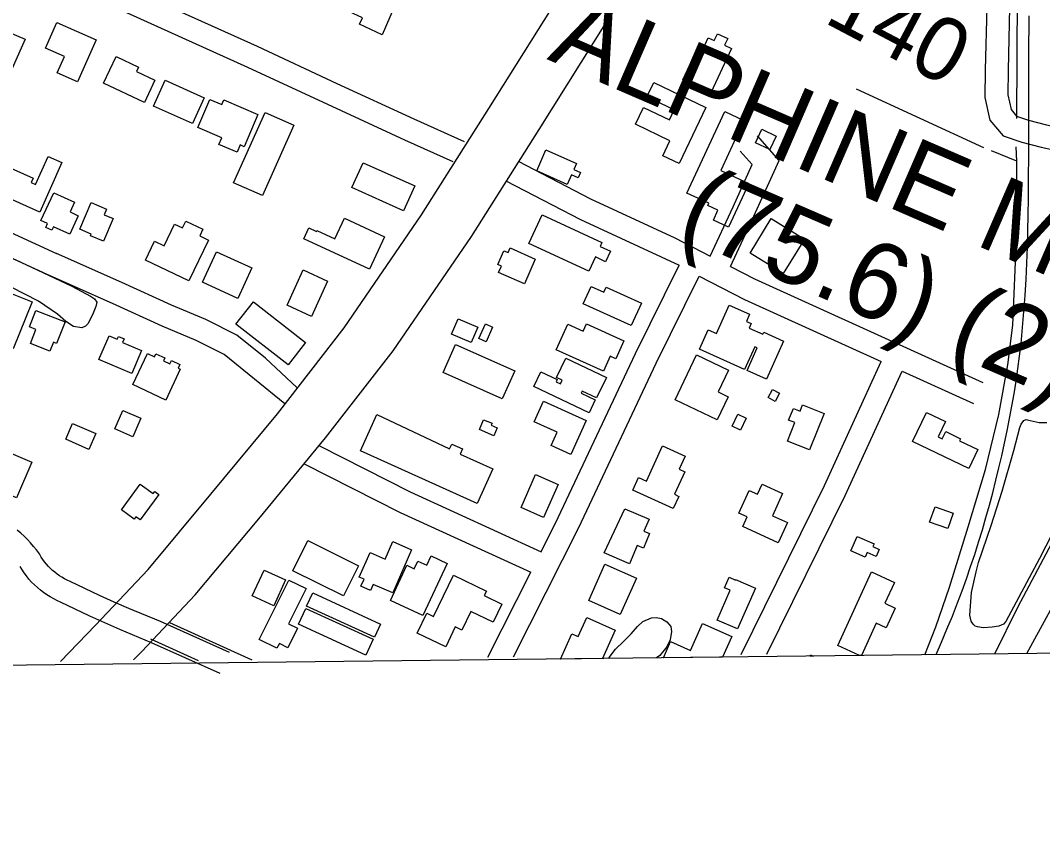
# Model space of a CAD drawing. Extents: x 3683402 to 3721514, y 487807 to 513565.
# Drawn here: x 3706941 to 3708279, y 493222 to 494291 of the extents above; entities that cross this region are included whole.
import ezdxf

# ---------------------------------------------------------------- set-up
doc = ezdxf.new("R2010")
doc.units = 0
for name, color, linetype in [('V-BLDG-OTLN', 7, 'Continuous'), ('V-CHAN-NAID', 7, 'Continuous'), ('V-GRID-FRAM', 7, 'Continuous'), ('V-LEVE-TOET', 7, 'Continuous'), ('V-RAIL-TRAK', 7, 'Continuous'), ('V-RIVR-RANG-IDEN', 7, 'Continuous'), ('V-ROAD-CNTR', 7, 'Continuous'), ('V-SITE-VEGE', 7, 'Continuous'), ('V-SURV-LINE', 7, 'Continuous'), ('V-TOPO-SHOR', 7, 'Continuous')]:
    doc.layers.add(name, color=color, linetype=linetype)

msp = doc.modelspace()

# ---------------------------------------------------------------- linework, layer by layer
at = {"layer": 'V-BLDG-OTLN'}
for p, q in [((3708011.4, 493472), (3708055.5, 493568.6)), ((3708055.5, 493568.6), (3708085.5, 493554.9)), ((3708085.5, 493554.9), (3708073, 493527.5)), ((3708073, 493527.5), (3708086.5, 493521.3)), ((3708086.5, 493521.3), (3708074.7, 493495.4)), ((3707671.4, 493483.8), (3707682.9, 493509.1)), ((3707682.9, 493509.1), (3707720, 493492.3)), ((3707720, 493492.3), (3707703.1, 493455.2)), ((3707818.7, 493465.7), (3707834.1, 493500.9)), ((3707834.1, 493500.9), (3707872.4, 493484.1)), ((3708061.5, 493501.5), (3708042.2, 493459.1)), ((3708074.7, 493495.4), (3708061.5, 493501.5)), ((3707648.3, 493454.5), (3707663.2, 493487.5)), ((3707663.2, 493487.5), (3707671.4, 493483.8)), ((3707783, 493456.1), (3707792.3, 493477.3)), ((3707792.3, 493477.3), (3707818.7, 493465.7)), ((3707872.4, 493484.1), (3707860.6, 493457)), ((3708039.7, 493459.1), (3708011.4, 493472)), ((3707703.1, 493455.2), (3707648.3, 493454.5)), ((3707860.6, 493457), (3707783, 493456.1)), ((3707974.9, 493458.3), (3707975.6, 493460)), ((3707979.7, 493458.4), (3707974.9, 493458.3)), ((3707975.6, 493460), (3707979.7, 493458.4)), ((3708042.2, 493459.1), (3708039.7, 493459.1))]:
    msp.add_line(p, q, dxfattribs=at)
for points in [[(3707356.7, 494301.7), (3707318.5, 494319.4), (3707331.8, 494347.9), (3707370.3, 494330), (3707363.3, 494314.8), (3707380.9, 494306.7), (3707392.8, 494337.8), (3707401.5, 494334.2), (3707402.3, 494335.9), (3707436.1, 494322.2), (3707415, 494272.3), (3707385.1, 494286.2), (3707389, 494294.7), (3707359.7, 494308.2)], [(3707040.3, 494265.7), (3707016, 494210.7), (3706989.3, 494222.5), (3706998.8, 494244), (3706974.1, 494255), (3706988.8, 494288.4)], [(3706892.2, 494212.3), (3706921.9, 494277.4), (3706947.4, 494266.5), (3706918, 494200.7)], [(3707872.1, 494254.5), (3707845.3, 494196.4), (3707808.5, 494213.4), (3707820.1, 494238.6), (3707826.6, 494235.7), (3707841.8, 494268.5), (3707849.6, 494264.8), (3707853.7, 494273.7), (3707867.2, 494267.4), (3707863.2, 494258.7)], [(3707103.6, 494183.8), (3707050.2, 494209.2), (3707066.7, 494243.9), (3707095.9, 494230.1), (3707093.1, 494224.2), (3707117.3, 494212.8)], [(3707130.6, 494212.9), (3707181.7, 494190), (3707166.4, 494156), (3707115.4, 494178.9)], [(3707770.3, 494210), (3707838.7, 494177.2), (3707803.6, 494103.8), (3707782.2, 494114), (3707791.6, 494133.6), (3707746.3, 494155.3), (3707756.8, 494177.2), (3707790.9, 494160.9), (3707797.1, 494173.9), (3707761.2, 494191)], [(3707207.5, 494187), (3707252.1, 494168.1), (3707234.2, 494125.8), (3707229, 494128), (3707225, 494118.5), (3707201.2, 494128.7), (3707204.9, 494137.4), (3707173.3, 494150.8), (3707189, 494187.7), (3707204.9, 494181)], [(3707813.7, 494065), (3707863.4, 494171.7), (3707888.5, 494160), (3707858.1, 494094.6), (3707895, 494077.4), (3707868.4, 494020.4), (3707848.4, 494029.6), (3707854.4, 494042.5), (3707841.1, 494048.8), (3707842.4, 494051.6)], [(3707299.2, 494153.8), (3707258, 494061.6), (3707220.3, 494078.4), (3707261.5, 494170.6)], [(3707911.9, 494148.6), (3707930.8, 494139.7), (3707922.5, 494122), (3707903.6, 494130.8)], [(3707629.3, 494121.5), (3707669.3, 494103.7), (3707665.8, 494095.8), (3707674.7, 494091.8), (3707671.6, 494084.9), (3707662.6, 494088.9), (3707657, 494076.4), (3707617.1, 494094.1)], [(3706966.5, 494040), (3706901, 494069.1), (3706916.1, 494103.2), (3706958.1, 494084.5), (3706955.5, 494078.7), (3706961.1, 494076.2), (3706977.5, 494113.1), (3706995.4, 494105.2)], [(3707442.7, 494041.7), (3707375.2, 494072.1), (3707389.9, 494104.7), (3707457.4, 494074.3)], [(3706968.1, 494029), (3706985.1, 494065.5), (3707012.1, 494053), (3707006.2, 494040.3), (3707017, 494035.3), (3707005.8, 494011.1), (3706984.7, 494020.9), (3706982.5, 494016.2), (3706974.5, 494019.9), (3706976.8, 494025)], [(3707018.8, 494017.6), (3707033.7, 494052.6), (3707053.9, 494044), (3707050.8, 494036.6), (3707062.8, 494031.5), (3707050.2, 494001.8), (3707033.1, 494009.1), (3707033.9, 494011.2)], [(3707187.3, 494003.4), (3707161.7, 493949.8), (3707104.8, 493977), (3707116.7, 494001.9), (3707129.3, 493995.9), (3707142.9, 494024.4), (3707153.5, 494019.4), (3707157.8, 494028.3), (3707180.1, 494017.6), (3707175.9, 494008.8)], [(3707398.1, 493965.1), (3707312.1, 494005.2), (3707318.8, 494019.5), (3707328.8, 494014.8), (3707329.3, 494015.9), (3707353, 494004.9), (3707365.7, 494032.3), (3707417.9, 494007.7)], [(3707624.2, 494036.4), (3707702.4, 494000.1), (3707700.2, 493995.2), (3707713.7, 493988.9), (3707707.3, 493975.1), (3707694, 493981.3), (3707685.2, 493962.5), (3707606.8, 493998.9)], [(3707924.3, 494031.6), (3707967.9, 494004.7), (3707940, 493959.5), (3707896.4, 493986.4)], [(3707198, 493988.1), (3707244.3, 493966.9), (3707226, 493926.9), (3707179.7, 493948.2)], [(3707601, 493946), (3707567.3, 493960.8), (3707571.1, 493969.4), (3707566.1, 493971.6), (3707574, 493989.5), (3707579.6, 493987.1), (3707582.2, 493993.1), (3707615.3, 493978.5)], [(3707290.3, 493918), (3707311.5, 493964.3), (3707343.4, 493949.7), (3707322.1, 493903.4)], [(3706956.7, 493922.4), (3706931.8, 493861.1), (3706894.8, 493876.2), (3706919.7, 493937.5)], [(3707754.2, 493920.8), (3707741, 493891.5), (3707678.1, 493919.9), (3707688.3, 493942.4), (3707704.9, 493935), (3707707.9, 493941.7)], [(3707291.7, 493840), (3707223.4, 493893.2), (3707246.2, 493922.4), (3707314.5, 493869.2)], [(3707889.4, 493833.8), (3707830.3, 493860.5), (3707841.7, 493885.9), (3707852.5, 493881), (3707869.2, 493918.2), (3707895.8, 493906.2), (3707891.6, 493896.9), (3707898.1, 493894), (3707895.4, 493888.1), (3707913.4, 493880), (3707914.5, 493882.6), (3707940.4, 493870.9), (3707918, 493821.1), (3707892.5, 493832.6), (3707905.9, 493862.4), (3707902.9, 493863.7)], [(3706999.7, 493896.4), (3706988.6, 493867.9), (3706984.4, 493869.5), (3706979.9, 493858), (3706954.4, 493868), (3706961.5, 493886.3), (3706953, 493889.6), (3706961.5, 493911.3)], [(3707514.3, 493900.3), (3707539.9, 493889.3), (3707531.2, 493869), (3707505.5, 493880)], [(3707541.5, 493874.4), (3707549.9, 493893.6), (3707559.2, 493889.5), (3707550.8, 493870.3)], [(3707704.4, 493831.6), (3707642.5, 493859.6), (3707657.7, 493893.2), (3707677.9, 493884), (3707682.3, 493893.7), (3707731.2, 493871.5), (3707720.6, 493848), (3707713.3, 493851.3)], [(3707086.9, 493828.6), (3707043.9, 493847), (3707057.2, 493878.1), (3707067.9, 493873.5), (3707069.5, 493877.2), (3707076.9, 493874.1), (3707074.8, 493869.3), (3707099.8, 493858.7)], [(3707571.9, 493795.5), (3707494.5, 493830), (3707510.8, 493866.7), (3707588.3, 493832.1)], [(3707131.6, 493793.7), (3707088.3, 493814), (3707107.4, 493854.9), (3707116.7, 493850.6), (3707118.5, 493854.4), (3707130.3, 493848.9), (3707128.5, 493845), (3707136.8, 493841.2), (3707138.9, 493845.7), (3707150, 493840.5), (3707147.6, 493835.4), (3707150.4, 493834.1)], [(3707853.6, 493768), (3707798.3, 493794.3), (3707826.2, 493853), (3707868.2, 493833), (3707854.6, 493804.6), (3707868, 493798.2)], [(3707685.9, 493777.1), (3707613.4, 493811.5), (3707622.5, 493830.8), (3707644, 493820.6), (3707642.6, 493817.7), (3707648.2, 493815), (3707650.5, 493819.8), (3707643.2, 493823.2), (3707655.3, 493848.6), (3707708.4, 493823.4), (3707695.6, 493796.5), (3707676.5, 493805.6), (3707675.2, 493803), (3707693.9, 493794.1)], [(3707920.1, 493797), (3707925.8, 493807.8), (3707935, 493803), (3707929.4, 493792.1)], [(3707682.1, 493767), (3707661.9, 493722.4), (3707635.9, 493734.2), (3707643.8, 493751.7), (3707613.7, 493765.3), (3707626, 493792.4)], [(3707945.3, 493740.1), (3707955, 493764.2), (3707947, 493767.4), (3707953.2, 493782.7), (3707961.9, 493779.2), (3707965.3, 493787.7), (3707993.7, 493776.3), (3707974.4, 493728.4)], [(3707065, 493756.1), (3707075.5, 493780.2), (3707099, 493770), (3707088.4, 493745.8)], [(3707559.6, 493703.6), (3707539.2, 493658.2), (3707386.3, 493727.3), (3707407.8, 493774.7), (3707503.1, 493729.9), (3707506.2, 493735.9), (3707519.8, 493729.8), (3707516.8, 493723)], [(3707873, 493759.7), (3707880.5, 493775.4), (3707891.4, 493770.2), (3707883.9, 493754.5)], [(3708182.8, 493704.1), (3708109.2, 493739.3), (3708127.5, 493777.6), (3708152.3, 493765.7), (3708142.7, 493745.4), (3708147.9, 493742.9), (3708152.6, 493752.6), (3708172.2, 493743.2), (3708170.8, 493740.3), (3708194.7, 493728.9)], [(3707030.9, 493729.2), (3707000.6, 493742.4), (3707009.6, 493763.1), (3707039.9, 493749.8)], [(3707561.1, 493747.1), (3707542.1, 493755.2), (3707547.7, 493768.1), (3707558.7, 493763.4), (3707557.5, 493760.7), (3707565.5, 493757.4)], [(3706936.3, 493665.8), (3706912.4, 493676.1), (3706917.1, 493687), (3706890.6, 493698.4), (3706907.4, 493737.4), (3706921, 493731.5), (3706919.5, 493728), (3706956.2, 493712.2)], [(3707795.9, 493651.5), (3707742.9, 493675.7), (3707750.5, 493692.3), (3707760.9, 493687.5), (3707782, 493733.6), (3707811.5, 493720.1), (3707803.7, 493703.1), (3707810.9, 493699.9), (3707797.4, 493670.3), (3707803.2, 493667.6)], [(3707645.1, 493683), (3707626, 493640), (3707596.6, 493653.1), (3707615.7, 493696.1)], [(3707073.4, 493650), (3707098.1, 493683.8), (3707115, 493671.4), (3707117, 493674.1), (3707122.4, 493670.2), (3707097.9, 493636.8), (3707092.3, 493640.9), (3707090, 493637.8)], [(3707939, 493671.2), (3707925.8, 493642.3), (3707945.4, 493633.4), (3707933.3, 493606.8), (3707886.8, 493628), (3707892.6, 493640.7), (3707881.6, 493645.8), (3707895.1, 493675.5), (3707906.3, 493670.4), (3707912.2, 493683.4)], [(3707732.6, 493651.1), (3707764.2, 493637.9), (3707757.6, 493622.2), (3707765, 493619.1), (3707756.8, 493599.6), (3707748.6, 493603.1), (3707738.6, 493579.3), (3707705.4, 493593.5)], [(3708138.7, 493653.8), (3708162.5, 493645.4), (3708155.4, 493625.4), (3708131.6, 493633.9)], [(3707364.3, 493537.2), (3707297.9, 493570.2), (3707317.5, 493609.7), (3707383.9, 493576.7)], [(3708036.9, 493615.2), (3708058.9, 493605.5), (3708057.2, 493601.8), (3708065.5, 493598.1), (3708061.4, 493588.7), (3708049.6, 493593.9), (3708047.1, 493588.1), (3708028.5, 493596.3)], [(3707453.3, 493597.5), (3707428.6, 493541.2), (3707403.2, 493552.3), (3707399.7, 493544.4), (3707387.1, 493549.9), (3707391.1, 493559), (3707384.8, 493561.8), (3707399, 493594), (3707418.7, 493585.4), (3707428.7, 493608.4)], [(3707499.9, 493579.7), (3707468.2, 493511.5), (3707425.8, 493531.2), (3707447.3, 493577.3), (3707456.9, 493572.8), (3707461.6, 493582.9), (3707473.3, 493577.5), (3707478.9, 493589.5)], [(3707244.8, 493537.1), (3707260.4, 493571), (3707288.4, 493558.1), (3707272.9, 493524.2)], [(3707747.6, 493560.6), (3707726.6, 493512.8), (3707685.2, 493531), (3707706.2, 493578.8)], [(3707277.1, 493468.5), (3707253.9, 493480), (3707292.6, 493558), (3707315.2, 493546.8), (3707292.3, 493500.7), (3707303.9, 493494.9), (3707291.2, 493469.3), (3707280.2, 493474.7)], [(3707498.1, 493470.4), (3707460.6, 493488.4), (3707473.1, 493514.5), (3707482, 493510.2), (3707508, 493564.4), (3707551.2, 493543.6), (3707548.2, 493537.5), (3707571.5, 493526.3), (3707560.2, 493502.8), (3707530.7, 493516.9), (3707519, 493492.5), (3707510.6, 493496.6)], [(3707903.6, 493547.4), (3707880.2, 493493.9), (3707853.3, 493505.6), (3707870.3, 493544.5), (3707863.1, 493547.6), (3707869.2, 493561.6), (3707877.3, 493558), (3707877.6, 493558.8)], [(3707404.6, 493483), (3707315.9, 493523.8), (3707323.9, 493541), (3707412.5, 493500.2)], [(3707393.6, 493459.7), (3707305.4, 493500.1), (3707314.9, 493520.8), (3707403.1, 493480.5)]]:
    msp.add_lwpolyline(points, close=True, dxfattribs=at)
at = {"layer": 'V-GRID-FRAM'}
msp.add_lwpolyline([(3687448, 511403.5), (3719130.8, 511772.1), (3719350.3, 493590.7), (3687651.7, 493221.8), (3687448, 511403.5)], dxfattribs=at)
at = {"layer": 'V-LEVE-TOET'}
msp.add_lwpolyline([(3708217.1, 493461.1), (3708247, 493522.4), (3708317.9, 493655.6), (3708381.1, 493770.3), (3708433.4, 493857), (3708496.8, 493957.1), (3708554.3, 494054.5)], dxfattribs=at)
at = {"layer": 'V-RAIL-TRAK'}
msp.add_lwpolyline([(3708140.1, 493460.3), (3708147.1, 493476.5), (3708154.3, 493493.6), (3708161.3, 493510.8), (3708168, 493528.1), (3708174, 493543.8), (3708179.7, 493559.7), (3708185.2, 493575.6), (3708190.6, 493591.6), (3708195.7, 493607.6), (3708200.6, 493623.7), (3708205.3, 493639.9), (3708209.8, 493656.1), (3708214.1, 493672.4), (3708218.2, 493688.7), (3708222.2, 493704.8), (3708226, 493720.9), (3708229.7, 493737.1), (3708233.1, 493753.3), (3708236.3, 493769.5), (3708239.3, 493785.8), (3708242.1, 493802.1), (3708244.8, 493818.5), (3708247.2, 493834.9), (3708249.4, 493851.3), (3708251.4, 493867.7), (3708253.3, 493888.7), (3708255, 493909.8), (3708256.5, 493930.9), (3708257.8, 493952), (3708258.8, 493973.1), (3708259.6, 493994.2), (3708260.3, 494015.3), (3708260.6, 494036.5), (3708260.8, 494057.6), (3708261.2, 494085.4), (3708261.5, 494113.2), (3708261.6, 494141.1), (3708261.3, 494193.1), (3708261.4, 494245.1), (3708261.7, 494297.1)], dxfattribs=at)
at = {"layer": 'V-ROAD-CNTR'}
for points in [[(3707089.2, 493453.2), (3707100, 493464.4), (3707169.9, 493538.6), (3707253.2, 493638.3), (3707340.5, 493744.3), (3707429.2, 493858.4), (3707531.6, 494008), (3707620.4, 494148.2), (3707711.8, 494294.6), (3707821.5, 494465.8), (3707935, 494652.3), (3708010.4, 494774), (3708062.3, 494861), (3708093.2, 494920.8), (3708118.3, 494977.3), (3708135.2, 495024.9), (3708151.7, 495081.4), (3708168.2, 495139.8)], [(3706993.5, 493451.3), (3707039.6, 493498.9), (3707108.4, 493571.9), (3707190.7, 493670.5), (3707277.6, 493775.9), (3707365.1, 493888.5), (3707466.3, 494036.3), (3707554.5, 494175.7), (3707646, 494322.2), (3707755.6, 494493.1), (3707868.9, 494679.4), (3707944.2, 494801), (3707995.2, 494886.4), (3708024.9, 494943.9), (3708044.9, 494988.9)], [(3707992.6, 494744.6), (3708074.4, 494698.6), (3708157.3, 494662.1), (3708181.4, 494647.6), (3708199.1, 494636.5), (3708203.1, 494623.6), (3708205.3, 494573.1), (3708207.7, 494436.9), (3708206.3, 494308.5), (3708204.2, 494226.4), (3708204, 494190.4), (3708210.5, 494160.5), (3708228, 494140), (3708252.4, 494131.8), (3708277.4, 494125.3), (3708309.8, 494118.1)], [(3708232.9, 494629.3), (3708235.3, 494574), (3708237.7, 494437), (3708236.3, 494308), (3708234.2, 494225.9), (3708234, 494193.5), (3708238.2, 494174.3), (3708245.5, 494165.8), (3708261, 494160.6), (3708284.5, 494154.5), (3708316.3, 494147.4)], [(3707507.7, 494106.1), (3707444.3, 494134.5), (3707343.5, 494181.1), (3707239.1, 494229.7), (3707067.2, 494307.1), (3706962.2, 494356.5)], [(3707522.8, 494132.3), (3707456.8, 494161.8), (3707356.1, 494208.3), (3707251.6, 494257), (3707148.4, 494303.5)], [(3706988.8, 493985.6), (3706609.4, 494159.9)], [(3706976.2, 493958.3), (3706596.8, 494132.7)], [(3707871, 493968.7), (3707901.6, 494034.6), (3707934.4, 494107.7), (3707906.1, 494139.9)], [(3707844.3, 493982.5), (3707874.3, 494047), (3707899.2, 494102.4), (3707883.6, 494120.1)], [(3707592.7, 494106.6), (3707687.6, 494057.5), (3707797.8, 494006.4), (3707844.3, 493982.5)], [(3707576.9, 494081.1), (3707674.4, 494030.5), (3707803.7, 493970.6)], [(3707303.3, 493810.3), (3707261.9, 493848.5), (3707224.5, 493879), (3707183.9, 493899.2), (3707139, 493918.2), (3707073.9, 493947.7), (3706988.6, 493985.7)], [(3707622.8, 493595.1), (3707645.3, 493640), (3707746.6, 493855), (3707803.7, 493970.6)], [(3707287.3, 493788.9), (3707208.1, 493853.6), (3707171.3, 493872), (3707126.9, 493890.7), (3707061.6, 493920.4), (3706976.4, 493958.2)], [(3707871, 493968.7), (3707902.3, 493952.6), (3708201.3, 493816.6)], [(3707586.9, 493457.2), (3707672.3, 493626.8), (3707773.6, 493842), (3707830, 493956.1)], [(3707830, 493956.1), (3707889.2, 493925.6), (3708068.1, 493844.2)], [(3707884.9, 493460.6), (3707993.9, 493681.8), (3708068.1, 493844.2)], [(3707918.5, 493461), (3708021, 493668.9), (3708095.4, 493831.8)], [(3708095.4, 493831.8), (3708188.9, 493789.3)], [(3707332.9, 493733.7), (3707451.4, 493673.4), (3707622.8, 493595.1)], [(3707312.6, 493710.4), (3707438.3, 493646.4), (3707609.3, 493568.3)], [(3707214.9, 493463.1), (3707124.7, 493503.5), (3707083.2, 493520.6), (3707064, 493529.1), (3707044.8, 493537.9), (3707025.7, 493546.9), (3707006.4, 493556.2), (3707002.4, 493558), (3706998.9, 493559.7), (3706995.6, 493561.6), (3706992.4, 493563.6), (3706989.2, 493565.8), (3706986.2, 493568.1), (3706983.3, 493570.6), (3706980.5, 493573.2), (3706977.8, 493575.9), (3706975.3, 493578.8), (3706972.9, 493581.7), (3706970.6, 493584.8), (3706968.5, 493588), (3706966, 493592.2), (3706962.1, 493597.4), (3706958.4, 493602.1), (3706954.5, 493606.7), (3706950.4, 493611.1), (3706946.1, 493615.4), (3706941.7, 493619.5), (3706937.1, 493623.4)], [(3707202.6, 493435.7), (3707112.9, 493475.9), (3707071.4, 493493), (3707051.6, 493501.7), (3707032.2, 493510.7), (3707012.8, 493519.8), (3706993.8, 493529), (3706989.6, 493530.9), (3706984.9, 493533.2), (3706980.3, 493535.8), (3706975.9, 493538.6), (3706971.6, 493541.6), (3706967.4, 493544.7), (3706963.4, 493548.1), (3706959.6, 493551.7), (3706955.9, 493555.4), (3706952.4, 493559.3), (3706949.1, 493563.4), (3706946, 493567.6), (3706943.1, 493572), (3706941, 493575.6)], [(3707553.1, 493456.8), (3707609.3, 493568.3)], [(3707136.6, 493502.3), (3707244.1, 493453.2)], [(3707111.5, 493480.8), (3707173.8, 493452.4)]]:
    msp.add_lwpolyline(points, dxfattribs=at)
at = {"layer": 'V-SITE-VEGE'}
for p, q in [((3707748.9, 493496.9), (3707756, 493503.8)), ((3707756, 493503.8), (3707767.3, 493508.3)), ((3707767.3, 493508.3), (3707773.5, 493509)), ((3707773.5, 493509), (3707780.5, 493507.7)), ((3707780.5, 493507.7), (3707787.4, 493503.4)), ((3707787.4, 493503.4), (3707792.8, 493497.1)), ((3707740.6, 493487.7), (3707748.9, 493496.9)), ((3707793.8, 493490.5), (3707791.7, 493479.6)), ((3707792.8, 493497.1), (3707793.8, 493490.5)), ((3707720.5, 493467.5), (3707730.8, 493477.4)), ((3707730.8, 493477.4), (3707740.6, 493487.7)), ((3707791.7, 493479.6), (3707787.7, 493470.4)), ((3707712.2, 493456.3), (3707720.5, 493467.5)), ((3707787.7, 493470.4), (3707778.2, 493459.2)), ((3707711.8, 493455.3), (3707712.2, 493456.3)), ((3707773.9, 493456), (3707711.8, 493455.3)), ((3707778.2, 493459.2), (3707773.9, 493456))]:
    msp.add_line(p, q, dxfattribs=at)
msp.add_lwpolyline([(3706934.2, 493978.1), (3707008.6, 493942.9), (3707033.1, 493930), (3707038.1, 493926.4), (3707041.2, 493922), (3707040, 493916.5), (3707035.5, 493905.6), (3707029.4, 493893.5), (3707026.6, 493890.8), (3707021.5, 493888.6), (3707010.9, 493890.3), (3707000.8, 493896.7), (3706989.6, 493906.3), (3706965.1, 493923.5), (3706910.6, 493951), (3706880.2, 493966.3), (3706868.7, 493979.8), (3706867.2, 493984.2), (3706866.9, 493989.7), (3706868.5, 493993.2), (3706870.1, 493994.7), (3706872.8, 493996.3), (3706883.4, 493996.1)], close=True, dxfattribs=at)
msp.add_lwpolyline([(3708341.9, 493715.6), (3708275.6, 493586.1), (3708231.3, 493503.7), (3708228.2, 493500.2), (3708222.3, 493497.6), (3708213.4, 493496.2), (3708201.7, 493495.2), (3708194.3, 493496.5), (3708191.3, 493497.7), (3708188.6, 493500), (3708185.9, 493504), (3708184.1, 493511.8), (3708186.5, 493541.6), (3708192.7, 493568.7), (3708195.6, 493581.1), (3708212.2, 493629.3), (3708226.4, 493674.2), (3708241.6, 493727.9), (3708249.8, 493757.7), (3708251.4, 493762.3), (3708255, 493766.9), (3708258.1, 493768.4), (3708263.1, 493767.2), (3708275.1, 493764.3), (3708285.2, 493764.5)], dxfattribs=at)
at = {"layer": 'V-SURV-LINE'}
msp.add_lwpolyline([(3708258.8, 493461.6), (3708478.1, 493862.9)], dxfattribs=at)
at = {"layer": 'V-TOPO-SHOR'}
for p, q in [((3708202.5, 494124.3), (3708035.9, 494201.2)), ((3708245.6, 494107), (3708212.6, 494120.4))]:
    msp.add_line(p, q, dxfattribs=at)
for points in [[(3708245.7, 494162.8), (3708246.8, 494325), (3708246.8, 494430.7)], [(3708125.2, 493460.1), (3708139.7, 493496.7), (3708157.7, 493548.8), (3708181.9, 493627.5), (3708204.5, 493702.6), (3708222, 493775), (3708233.9, 493839.8), (3708240.5, 493892.1), (3708245.3, 494005.4), (3708245.6, 494107), (3708244.7, 494125.6)]]:
    msp.add_lwpolyline(points, dxfattribs=at)

# ---------------------------------------------------------------- texts
at = {"layer": 'V-CHAN-NAID'}
for s, p in [('ALPHINE MUD', (3707629.6, 494240.7)), ('(75.6) (2)', (3707797.6, 494011.2))]:
    msp.add_text(s, height=100, rotation=336.5597, dxfattribs=at).set_placement(p)
at = {"layer": 'V-RIVR-RANG-IDEN'}
msp.add_text('D-140', height=83, rotation=332.1583, dxfattribs=at).set_placement((3707887.7, 494344.3))

doc.saveas('drawing.dxf')
